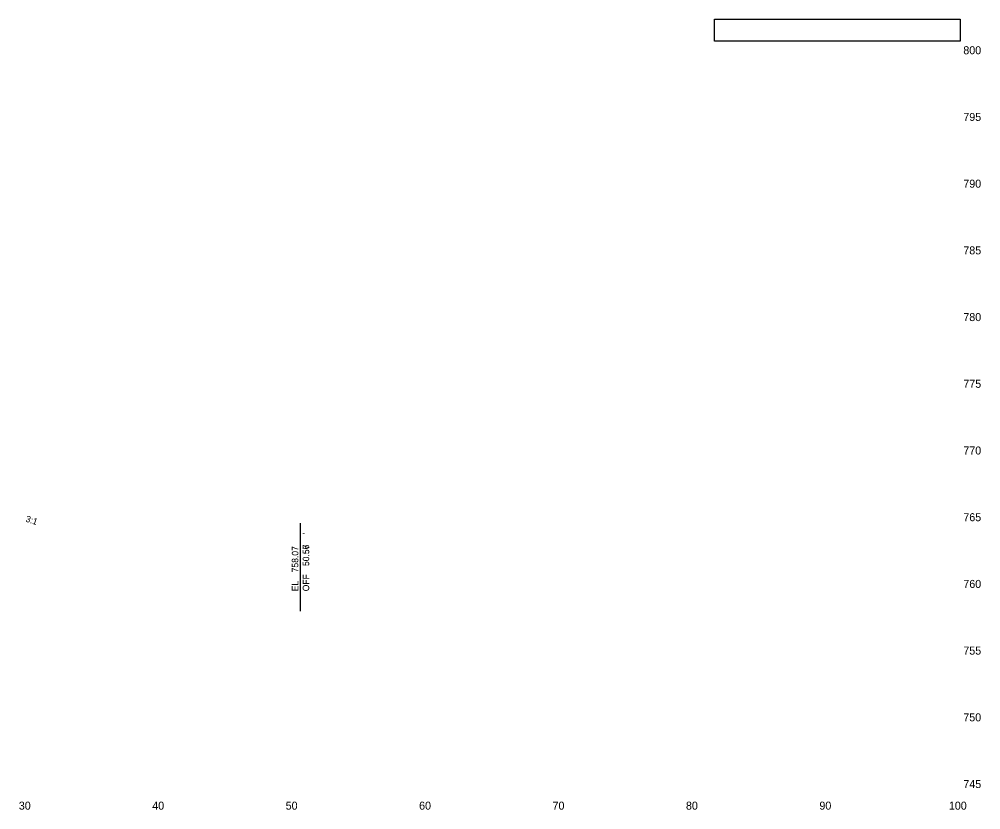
# Model space of a CAD drawing. Extents: x -42 to 102, y 742 to 803.
# Drawn here: x 29.5 to 101.5, y 743.5 to 802.7 of the extents above; entities that cross this region are included whole.
import ezdxf

# ---------------------------------------------------------------- set-up
doc = ezdxf.new("R2010")
doc.units = 0
for name, color, linetype in [('Border-Profile bottom shape', 7, 'Continuous'), ('XS-Feature Text', 7, 'Continuous'), ('XS-Segment Text', 7, 'Continuous'), ('XS-Text', 7, 'Continuous')]:
    doc.layers.add(name, color=color, linetype=linetype)

msp = doc.modelspace()

# ---------------------------------------------------------------- linework, layer by layer
at = {"layer": 'Border-Profile bottom shape'}
msp.add_lwpolyline([(81.6, 802.74), (100, 802.74), (100, 801.1), (81.6, 801.1)], close=True, dxfattribs=at)
msp.add_circle((100, 802.74), 0.005, dxfattribs=at)
msp.add_circle((100, 802.74), 0.005, dxfattribs=at)
msp.add_circle((100, 802.74), 0.005, dxfattribs=at)
msp.add_circle((100, 802.74), 0.005, dxfattribs=at)
msp.add_circle((100, 802.74), 0.005, dxfattribs=at)
msp.add_circle((100, 802.74), 0.005, dxfattribs=at)
at = {"layer": 'XS-Feature Text'}
for p, q in [((50.561, 758.367), (50.561, 764.967)), ((50.567, 758.366), (50.567, 764.966)), ((50.568, 758.366), (50.568, 764.966))]:
    msp.add_line(p, q, dxfattribs=at)

# ---------------------------------------------------------------- texts
for s, p in [("'", (51.209, 764.129)), ("'", (51.215, 764.128)), ("'", (51.216, 764.128)), ('758.07', (50.393, 761.287)), ('758.07', (50.399, 761.287)), ('758.07', (50.4, 761.287)), ('50.56', (51.209, 761.761)), ('50.57', (51.215, 761.76)), ('50.57', (51.216, 761.76)), ('OFF ', (51.209, 759.867)), ('OFF ', (51.215, 759.866)), ('OFF ', (51.216, 759.866)), ('EL ', (50.393, 759.867)), ('EL ', (50.399, 759.866)), ('EL ', (50.4, 759.866))]:
    msp.add_text(s, height=0.48, rotation=90, dxfattribs=at).set_placement(p)
at = {"layer": 'XS-Segment Text'}
msp.add_text('3:1', height=0.48, rotation=341.56677, dxfattribs=at).set_placement((29.92, 765.104))
at = {"layer": 'XS-Text'}
for s, p in [('800', (100.24, 800.12)), ('795', (100.24, 795.12)), ('790', (100.24, 790.12)), ('785', (100.24, 785.12)), ('780', (100.24, 780.12)), ('775', (100.24, 775.12)), ('770', (100.24, 770.12)), ('765', (100.24, 765.12)), ('760', (100.24, 760.12)), ('755', (100.24, 755.12)), ('750', (100.24, 750.12)), ('745', (100.24, 745.12)), ('30', (29.453, 743.5)), ('40', (39.453, 743.5)), ('50', (49.453, 743.5)), ('60', (59.453, 743.5)), ('70', (69.453, 743.5)), ('80', (79.453, 743.5)), ('90', (89.453, 743.5)), ('100', (99.157, 743.5))]:
    msp.add_text(s, height=0.6, dxfattribs=at).set_placement(p)

doc.saveas('drawing.dxf')
